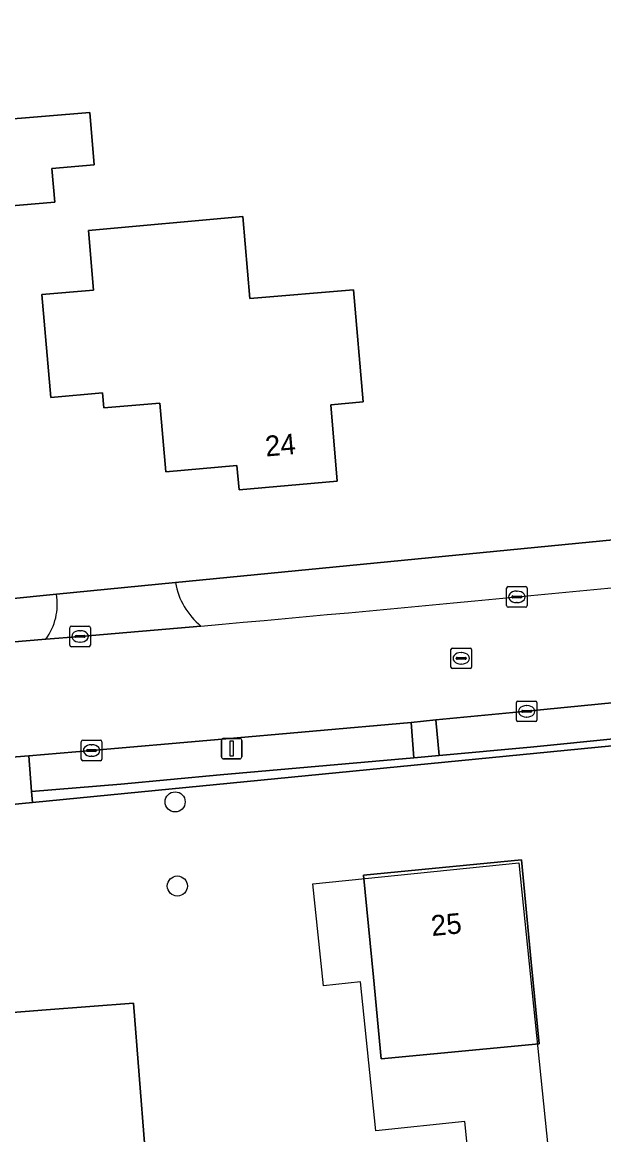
# Model space of a CAD drawing. Extents: x 162661 to 163484, y 380247 to 381230.
# Drawn here: x 163128.5 to 163156.8, y 380754.9 to 380809.1 of the extents above; entities that cross this region are included whole.
import ezdxf

# ---------------------------------------------------------------- set-up
doc = ezdxf.new("R2010")
doc.units = 0
for name, color, linetype in [('IMGEO_Berm_groen', 7, 'Continuous'), ('IMGEO_Boom', 7, 'Continuous'), ('IMGEO_Erf', 7, 'Continuous'), ('IMGEO_Groenvoorziening', 7, 'Continuous'), ('IMGEO_Haag', 7, 'Continuous'), ('IMGEO_Kolk', 7, 'Continuous'), ('IMGEO_Lichtmast', 7, 'Continuous'), ('IMGEO_Pand', 7, 'Continuous'), ('IMGEO_Pand_nummerreeks', 7, 'Continuous'), ('IMGEO_Pand_vergunning_verleend', 7, 'Continuous'), ('IMGEO_Parkeervlak_halfverhard', 7, 'Continuous'), ('IMGEO_Rijbaan_lokaal_gesloten', 7, 'Continuous'), ('IMGEO_Rijbaan_lokaal_halfverhard', 7, 'Continuous'), ('IMGEO_Rioolput', 7, 'Continuous'), ('IMGEO_Voetpad_open', 7, 'Continuous')]:
    doc.layers.add(name, color=color, linetype=linetype)

msp = doc.modelspace()

# ---------------------------------------------------------------- linework, layer by layer
at = {"layer": 'IMGEO_Berm_groen'}
msp.add_lwpolyline([(163169.717, 380785.094), (163135.951, 380781.798)], dxfattribs=at)
for centre, radius, start, end in [((162944.766, 382949.195), 2178.026, 275.068746, 275.934695), ((163139.44, 380782.434), 3.546, 190.3309, 230.7708)]:
    msp.add_arc(centre, radius, start, end, dxfattribs=at)
at = {"layer": 'IMGEO_Boom'}
for centre in [(163135.94, 380771.125), (163136.047, 380767.031)]:
    msp.add_circle(centre, 0.489, dxfattribs=at)
at = {"layer": 'IMGEO_Erf'}
for points in [[(163127.759, 380780.998), (163130.169, 380781.233), (163135.951, 380781.798), (163169.717, 380785.094), (163173.288, 380785.441), (163177.861, 380785.922), (163181.694, 380786.429), (163187.844, 380787.314), (163203.861, 380789.941), (163216.422, 380792.223), (163223.823, 380793.651), (163227.184, 380794.299), (163228.163, 380794.477), (163230.868, 380795.207), (163233.609, 380795.947), (163234.804, 380796.412), (163249.489, 380802.652), (163259.718, 380807.867), (163268.827, 380813.377), (163271.872, 380815.173), (163286.296, 380824.946), (163299.265, 380834.754)], [(163177.253, 380775.814), (163129.006, 380771.1), (163125.314, 380770.739), (163110.198, 380769.262)]]:
    msp.add_lwpolyline(points, dxfattribs=at)
for points in [[(163127.262, 380804.312), (163131.789, 380804.687), (163132, 380802.136), (163129.943, 380801.965), (163130.08, 380800.311), (163127.61, 380800.107)], [(163144.626, 380796.055), (163145.084, 380790.6), (163143.508, 380790.459), (163143.825, 380786.737), (163139.054, 380786.313), (163138.949, 380787.494), (163135.492, 380787.187), (163135.199, 380790.538), (163132.467, 380790.303), (163132.409, 380791.035), (163129.885, 380790.818), (163129.449, 380795.82), (163131.975, 380796.041), (163131.722, 380798.943), (163139.239, 380799.621), (163139.574, 380795.631)], [(163153.647, 380759.35), (163145.972, 380758.611), (163145.589, 380762.59), (163145.11, 380767.567), (163152.785, 380768.306), (163153.264, 380763.329)], [(163134.745, 380750.815), (163131.983, 380750.596), (163131.749, 380753.541), (163131.296, 380753.505), (163130.265, 380753.423), (163123.198, 380752.863), (163123.084, 380754.308), (163122.884, 380756.841), (163118.577, 380756.5), (163118.388, 380756.485), (163118.032, 380760.981), (163116.527, 380760.862), (163116.243, 380764.451), (163117.749, 380764.571), (163117.662, 380765.585), (163122.247, 380765.936), (163122.326, 380764.93), (163125.816, 380765.207), (163126.173, 380760.722), (163129.663, 380760.999), (163133.909, 380761.336)]]:
    msp.add_lwpolyline(points, close=True, dxfattribs=at)
at = {"layer": 'IMGEO_Groenvoorziening'}
for points in [[(163130.169, 380781.233), (163127.759, 380780.998), (163127.927, 380778.898), (163129.656, 380779.042)], [(163162.866, 380774.747), (163161.96, 380774.658), (163153.238, 380773.792), (163148.788, 380773.381), (163147.547, 380773.273), (163138.129, 380772.447), (163133.305, 380771.987), (163128.949, 380771.637), (163129.006, 380771.1), (163177.253, 380775.814)]]:
    msp.add_lwpolyline(points, dxfattribs=at)
msp.add_arc((163127.231, 380780.765), 2.975, 324.6016, 9.0427, dxfattribs=at)
at = {"layer": 'IMGEO_Haag'}
msp.add_lwpolyline([(163162.866, 380774.747), (163161.96, 380774.658), (163153.238, 380773.792), (163148.788, 380773.381), (163147.547, 380773.273), (163138.129, 380772.447), (163133.305, 380771.987), (163128.949, 380771.637), (163129.006, 380771.1), (163177.253, 380775.814)], dxfattribs=at)
at = {"layer": 'IMGEO_Kolk'}
for p, q in [((163152.066, 380780.679), (163152.066, 380781.531)), ((163152.141, 380781.605), (163152.993, 380781.605)), ((163152.368, 380781.148), (163152.766, 380781.148)), ((163152.554, 380781.385), (163152.579, 380781.385)), ((163153.067, 380781.531), (163153.067, 380780.679)), ((163152.993, 380780.605), (163152.141, 380780.605)), ((163152.325, 380781.099), (163152.325, 380781.111)), ((163152.763, 380781.062), (163152.365, 380781.062)), ((163152.577, 380780.825), (163152.552, 380780.825)), ((163152.809, 380781.111), (163152.809, 380781.099)), ((163130.815, 380778.754), (163130.815, 380779.606)), ((163130.89, 380779.68), (163131.742, 380779.68)), ((163131.816, 380779.606), (163131.816, 380778.754)), ((163131.074, 380779.174), (163131.074, 380779.186)), ((163131.512, 380779.137), (163131.114, 380779.137)), ((163131.117, 380779.223), (163131.515, 380779.223)), ((163131.303, 380779.46), (163131.328, 380779.46)), ((163131.558, 380779.186), (163131.558, 380779.174)), ((163131.742, 380778.68), (163130.89, 380778.68)), ((163131.326, 380778.9), (163131.301, 380778.9)), ((163152.543, 380775.108), (163152.543, 380775.96)), ((163152.618, 380776.034), (163153.47, 380776.034)), ((163153.031, 380775.814), (163153.056, 380775.814)), ((163153.544, 380775.96), (163153.544, 380775.108)), ((163152.802, 380775.528), (163152.802, 380775.54)), ((163153.24, 380775.491), (163152.842, 380775.491)), ((163152.845, 380775.577), (163153.243, 380775.577)), ((163153.054, 380775.254), (163153.029, 380775.254)), ((163153.286, 380775.54), (163153.286, 380775.528)), ((163153.47, 380775.034), (163152.618, 380775.034)), ((163131.449, 380774.129), (163132.301, 380774.129)), ((163131.374, 380773.203), (163131.374, 380774.055)), ((163131.633, 380773.623), (163131.633, 380773.635)), ((163132.071, 380773.586), (163131.673, 380773.586)), ((163131.676, 380773.672), (163132.074, 380773.672)), ((163131.862, 380773.909), (163131.887, 380773.909)), ((163132.117, 380773.635), (163132.117, 380773.623)), ((163132.375, 380774.055), (163132.375, 380773.203)), ((163132.301, 380773.129), (163131.449, 380773.129)), ((163131.885, 380773.349), (163131.86, 380773.349))]:
    msp.add_line(p, q, dxfattribs=at)
for points in [[(163152.066, 380780.679), (163152.066, 380781.531)], [(163152.141, 380781.605), (163152.993, 380781.605)], [(163153.067, 380781.531), (163153.067, 380780.679)], [(163152.993, 380780.605), (163152.141, 380780.605)], [(163130.815, 380778.754), (163130.815, 380779.606)], [(163130.89, 380779.68), (163131.742, 380779.68)], [(163131.816, 380779.606), (163131.816, 380778.754)], [(163131.742, 380778.68), (163130.89, 380778.68)], [(163152.543, 380775.108), (163152.543, 380775.96)], [(163152.618, 380776.034), (163153.47, 380776.034)], [(163153.544, 380775.96), (163153.544, 380775.108)], [(163153.47, 380775.034), (163152.618, 380775.034)], [(163131.449, 380774.129), (163132.301, 380774.129)], [(163131.374, 380773.203), (163131.374, 380774.055)], [(163132.375, 380774.055), (163132.375, 380773.203)], [(163132.301, 380773.129), (163131.449, 380773.129)]]:
    msp.add_lwpolyline(points, dxfattribs=at)
for centre, radius, start, end in [((163152.143, 380781.529), 0.0765, 91.552, 178.448), ((163152.143, 380781.529), 0.0765, 91.552, 178.448), ((163152.365, 380781.108), 0.0403, 85.8775, 175.7526), ((163152.77, 380781.11), 0.0386, 1.7309, 96.639), ((163152.991, 380781.529), 0.0765, 1.552, 88.448), ((163152.991, 380781.529), 0.0765, 1.552, 88.448), ((163152.143, 380780.681), 0.0765, 181.552, 268.448), ((163152.143, 380780.681), 0.0765, 181.552, 268.448), ((163152.362, 380781.098), 0.0366, 178.938, 274.7102), ((163152.766, 380781.105), 0.043, 264.8664, 352.4533), ((163152.991, 380780.681), 0.0765, 271.552, 358.448), ((163152.991, 380780.681), 0.0765, 271.552, 358.448), ((163130.892, 380779.604), 0.0765, 91.552, 178.448), ((163130.892, 380779.604), 0.0765, 91.552, 178.448), ((163131.74, 380779.604), 0.0765, 1.552, 88.448), ((163131.74, 380779.604), 0.0765, 1.552, 88.448), ((163131.114, 380779.183), 0.0403, 85.8775, 175.7526), ((163131.111, 380779.173), 0.0366, 178.938, 274.7102), ((163131.515, 380779.18), 0.043, 264.8664, 352.4533), ((163131.519, 380779.185), 0.0386, 1.7309, 96.639), ((163130.892, 380778.756), 0.0765, 181.552, 268.448), ((163130.892, 380778.756), 0.0765, 181.552, 268.448), ((163131.74, 380778.756), 0.0765, 271.552, 358.448), ((163131.74, 380778.756), 0.0765, 271.552, 358.448), ((163152.62, 380775.958), 0.0765, 91.552, 178.448), ((163152.62, 380775.958), 0.0765, 91.552, 178.448), ((163153.468, 380775.958), 0.0765, 1.552, 88.448), ((163153.468, 380775.958), 0.0765, 1.552, 88.448), ((163152.842, 380775.537), 0.0403, 85.8775, 175.7526), ((163152.839, 380775.527), 0.0366, 178.938, 274.7102), ((163153.243, 380775.534), 0.043, 264.8664, 352.4533), ((163153.247, 380775.539), 0.0386, 1.7309, 96.639), ((163152.62, 380775.11), 0.0765, 181.552, 268.448), ((163152.62, 380775.11), 0.0765, 181.552, 268.448), ((163153.468, 380775.11), 0.0765, 271.552, 358.448), ((163153.468, 380775.11), 0.0765, 271.552, 358.448), ((163131.451, 380774.053), 0.0765, 91.552, 178.448), ((163131.451, 380774.053), 0.0765, 91.552, 178.448), ((163132.299, 380774.053), 0.0765, 1.552, 88.448), ((163132.299, 380774.053), 0.0765, 1.552, 88.448), ((163131.673, 380773.632), 0.0403, 85.8775, 175.7526), ((163131.67, 380773.622), 0.0366, 178.938, 274.7102), ((163132.074, 380773.629), 0.043, 264.8664, 352.4533), ((163132.078, 380773.634), 0.0386, 1.7309, 96.639), ((163131.451, 380773.205), 0.0765, 181.552, 268.448), ((163131.451, 380773.205), 0.0765, 181.552, 268.448), ((163132.299, 380773.205), 0.0765, 271.552, 358.448), ((163132.299, 380773.205), 0.0765, 271.552, 358.448)]:
    msp.add_arc(centre, radius, start, end, dxfattribs=at)
for centre, major_axis, ratio, start_param, end_param in [((163152.553, 380781.105), (-0.387, 0.002), 0.722429, 4.712389, 7.853982), ((163152.578, 380781.105), (-0.39, 0.002), 0.717154, 1.570796, 4.712389), ((163131.302, 380779.18), (-0.387, 0.002), 0.722429, 4.712389, 7.853982), ((163131.327, 380779.18), (-0.39, 0.002), 0.717154, 1.570796, 4.712389), ((163153.03, 380775.534), (-0.387, 0.002), 0.722429, 4.712389, 7.853982), ((163153.055, 380775.534), (-0.39, 0.002), 0.717154, 1.570796, 4.712389), ((163131.861, 380773.629), (-0.387, 0.002), 0.722429, 4.712389, 7.853982), ((163131.886, 380773.629), (-0.39, 0.002), 0.717154, 1.570796, 4.712389)]:
    msp.add_ellipse(centre, major_axis=major_axis, ratio=ratio, start_param=start_param, end_param=end_param, dxfattribs=at)
at = {"layer": 'IMGEO_Lichtmast'}
for p, q in [((163138.193, 380773.319), (163138.193, 380774.119)), ((163138.193, 380774.119), (163138.193, 380773.319)), ((163138.293, 380774.219), (163139.083, 380774.219)), ((163139.083, 380774.219), (163138.293, 380774.219)), ((163139.183, 380774.119), (163139.183, 380773.319)), ((163139.183, 380773.319), (163139.183, 380774.119)), ((163139.083, 380773.219), (163138.293, 380773.219)), ((163138.293, 380773.219), (163139.083, 380773.219))]:
    msp.add_line(p, q, dxfattribs=at)
msp.add_lwpolyline([(163138.613, 380774.094), (163138.763, 380774.094), (163138.763, 380773.344), (163138.613, 380773.344), (163138.613, 380774.094)], dxfattribs=at)
for centre, start, end in [((163138.293, 380774.119), 90, 180), ((163138.293, 380774.119), 90, 180), ((163139.083, 380774.119), 0, 90), ((163139.083, 380774.119), 360, 90), ((163138.293, 380773.319), 180, 270), ((163138.293, 380773.319), 180, 270), ((163139.083, 380773.319), 270, 0), ((163139.083, 380773.319), 270, 0)]:
    msp.add_arc(centre, 0.1, start, end, dxfattribs=at)
at = {"layer": 'IMGEO_Pand'}
for points in [[(163127.262, 380804.312), (163127.61, 380800.107), (163130.08, 380800.311), (163129.943, 380801.965), (163132, 380802.136), (163131.789, 380804.687)], [(163144.626, 380796.055), (163139.574, 380795.631), (163139.239, 380799.621), (163131.722, 380798.943), (163131.975, 380796.041), (163129.449, 380795.82), (163129.885, 380790.818), (163132.409, 380791.035), (163132.467, 380790.303), (163135.199, 380790.538), (163135.492, 380787.187), (163138.949, 380787.494), (163139.054, 380786.313), (163143.825, 380786.737), (163143.508, 380790.459), (163145.084, 380790.6)], [(163153.264, 380763.329), (163152.785, 380768.306), (163145.11, 380767.567), (163145.589, 380762.59), (163145.972, 380758.611), (163153.647, 380759.35)], [(163129.663, 380760.999), (163126.173, 380760.722), (163125.816, 380765.207), (163122.326, 380764.93), (163122.247, 380765.936), (163117.662, 380765.585), (163117.749, 380764.571), (163116.243, 380764.451), (163116.527, 380760.862), (163118.032, 380760.981), (163118.388, 380756.485), (163118.577, 380756.5), (163122.884, 380756.841), (163123.084, 380754.308), (163123.198, 380752.863), (163130.265, 380753.423), (163131.296, 380753.505), (163131.749, 380753.541), (163131.983, 380750.596), (163134.745, 380750.815), (163133.909, 380761.336)]]:
    msp.add_lwpolyline(points, close=True, dxfattribs=at)
at = {"layer": 'IMGEO_Pand_vergunning_verleend'}
msp.add_lwpolyline([(163142.642, 380767.14), (163152.665, 380768.167), (163154.161, 380753.573), (163150.272, 380753.174), (163150.027, 380755.561), (163145.699, 380755.117), (163144.957, 380762.359), (163143.151, 380762.174)], close=True, dxfattribs=at)
at = {"layer": 'IMGEO_Parkeervlak_halfverhard'}
for points in [[(163161.816, 380776.396), (163153.044, 380775.534), (163148.627, 380775.118), (163148.788, 380773.381), (163153.238, 380773.792), (163161.96, 380774.658)], [(163147.426, 380774.997), (163137.859, 380774.152), (163131.875, 380773.629), (163128.826, 380773.368), (163128.949, 380771.637), (163133.305, 380771.987), (163138.129, 380772.447), (163147.547, 380773.273)]]:
    msp.add_lwpolyline(points, close=True, dxfattribs=at)
at = {"layer": 'IMGEO_Rijbaan_lokaal_gesloten'}
msp.add_lwpolyline([(163137.197, 380779.687), (163131.316, 380779.18), (163129.656, 380779.042), (163127.927, 380778.898), (163124.447, 380778.625), (163122.096, 380778.441), (163121.228, 380778.336), (163113.611, 380777.772), (163111.385, 380777.62), (163111.403, 380777.32), (163111.711, 380772.35), (163111.73, 380772.04), (163125.124, 380773.071), (163128.826, 380773.368), (163131.875, 380773.629), (163137.859, 380774.152), (163147.426, 380774.997), (163148.627, 380775.118), (163153.044, 380775.534), (163161.816, 380776.396), (163162.732, 380776.494)], dxfattribs=at)
msp.add_arc((162944.766, 382949.195), 2178.026, 275.068746, 275.934695, dxfattribs=at)
at = {"layer": 'IMGEO_Rijbaan_lokaal_halfverhard'}
for points in [[(163135.951, 380781.798), (163130.169, 380781.233)], [(163129.656, 380779.042), (163131.316, 380779.18), (163137.197, 380779.687)]]:
    msp.add_lwpolyline(points, dxfattribs=at)
for centre, radius, start, end in [((163139.44, 380782.434), 3.546, 190.3309, 230.7708), ((163127.231, 380780.765), 2.975, 324.6016, 9.0427)]:
    msp.add_arc(centre, radius, start, end, dxfattribs=at)
at = {"layer": 'IMGEO_Rioolput'}
for p, q in [((163149.361, 380777.689), (163149.361, 380778.541)), ((163149.436, 380778.615), (163150.288, 380778.615)), ((163150.362, 380778.541), (163150.362, 380777.689)), ((163149.62, 380778.109), (163149.62, 380778.121)), ((163150.058, 380778.072), (163149.66, 380778.072)), ((163149.663, 380778.158), (163150.061, 380778.158)), ((163149.849, 380778.395), (163149.874, 380778.395)), ((163150.104, 380778.121), (163150.104, 380778.109)), ((163150.288, 380777.615), (163149.436, 380777.615)), ((163149.872, 380777.835), (163149.847, 380777.835))]:
    msp.add_line(p, q, dxfattribs=at)
for points in [[(163149.361, 380777.689), (163149.361, 380778.541)], [(163149.436, 380778.615), (163150.288, 380778.615)], [(163150.362, 380778.541), (163150.362, 380777.689)], [(163150.288, 380777.615), (163149.436, 380777.615)]]:
    msp.add_lwpolyline(points, dxfattribs=at)
for centre, radius, start, end in [((163149.438, 380778.539), 0.0765, 91.552, 178.448), ((163149.438, 380778.539), 0.0765, 91.552, 178.448), ((163150.286, 380778.539), 0.0765, 1.552, 88.448), ((163150.286, 380778.539), 0.0765, 1.552, 88.448), ((163149.66, 380778.118), 0.0403, 85.8775, 175.7526), ((163149.657, 380778.108), 0.0366, 178.938, 274.7102), ((163150.061, 380778.115), 0.043, 264.8664, 352.4533), ((163150.065, 380778.12), 0.0386, 1.7309, 96.639), ((163149.438, 380777.691), 0.0765, 181.552, 268.448), ((163149.438, 380777.691), 0.0765, 181.552, 268.448), ((163150.286, 380777.691), 0.0765, 271.552, 358.448), ((163150.286, 380777.691), 0.0765, 271.552, 358.448)]:
    msp.add_arc(centre, radius, start, end, dxfattribs=at)
for centre, major_axis, ratio, start_param, end_param in [((163149.848, 380778.115), (-0.387, 0.002), 0.722429, 4.712389, 7.853982), ((163149.873, 380778.115), (-0.39, 0.002), 0.717154, 1.570796, 4.712389)]:
    msp.add_ellipse(centre, major_axis=major_axis, ratio=ratio, start_param=start_param, end_param=end_param, dxfattribs=at)
at = {"layer": 'IMGEO_Voetpad_open'}
for points in [[(163147.547, 380773.273), (163148.788, 380773.381), (163148.627, 380775.118), (163147.426, 380774.997)], [(163125.314, 380770.739), (163129.006, 380771.1), (163128.949, 380771.637), (163128.826, 380773.368), (163125.124, 380773.071), (163125.276, 380771.365)]]:
    msp.add_lwpolyline(points, close=True, dxfattribs=at)

# ---------------------------------------------------------------- texts
at = {"layer": 'IMGEO_Pand_nummerreeks'}
for s, rotation, p in [('24', 5.0764, (163140.362, 380787.935)), ('25', 5.4999, (163148.439, 380764.593))]:
    msp.add_text(s, height=1, rotation=rotation, dxfattribs=at).set_placement(p)

doc.saveas('drawing.dxf')
